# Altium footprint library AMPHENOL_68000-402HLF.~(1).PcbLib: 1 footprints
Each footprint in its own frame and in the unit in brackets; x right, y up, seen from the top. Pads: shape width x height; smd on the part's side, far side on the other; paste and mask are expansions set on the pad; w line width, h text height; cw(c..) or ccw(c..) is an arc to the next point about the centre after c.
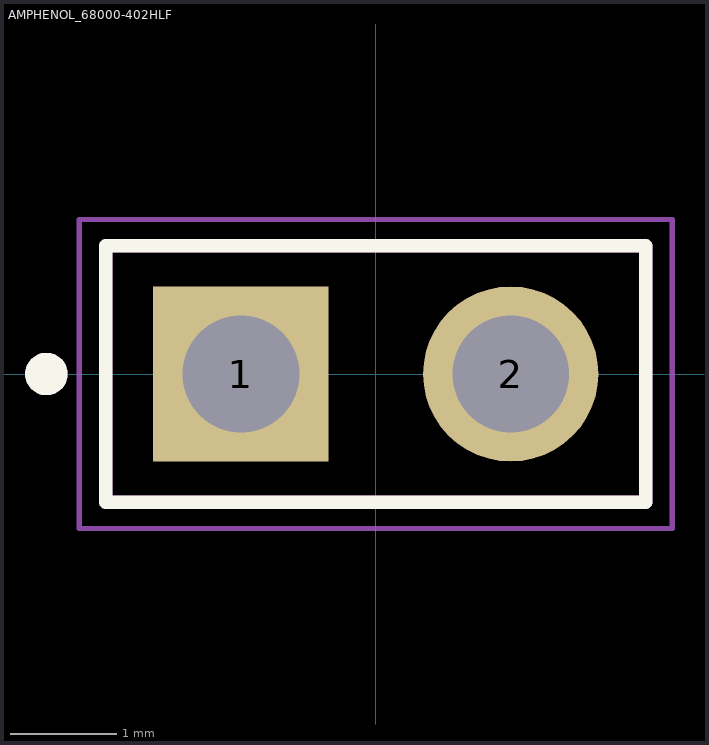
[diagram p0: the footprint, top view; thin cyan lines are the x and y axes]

## AMPHENOL_68000-402HLF [mm]
height 10.8
pads (2):
  rect 1.65x1.65 / inner round 1.65 / far side rect 1.65x1.65 hole 1.1: 1(-1.27,0)
  round 1.65 hole 1.1: 2(1.27,0)
Top Overlay:
  circle w0.2: c-3.1,0 r0.1
  lines w0.127: -2.54,-1.205 -2.54,1.205 2.54,1.205 2.54,-1.205 -2.54,-1.205
Mechanical 13:
  circle w0.2: c-3.1,0 r0.1
  lines w0.127: -2.54,-1.205 -2.54,1.205 2.54,1.205 2.54,-1.205 -2.54,-1.205
Mechanical 15:
  lines w0.05: -2.79,-1.455 -2.79,1.455 2.79,1.455 2.79,-1.455 -2.79,-1.455
3D body "step_temp.STEP": height 8.39, standoff -2.41, extent -2.54,-1.205 2.54,1.205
